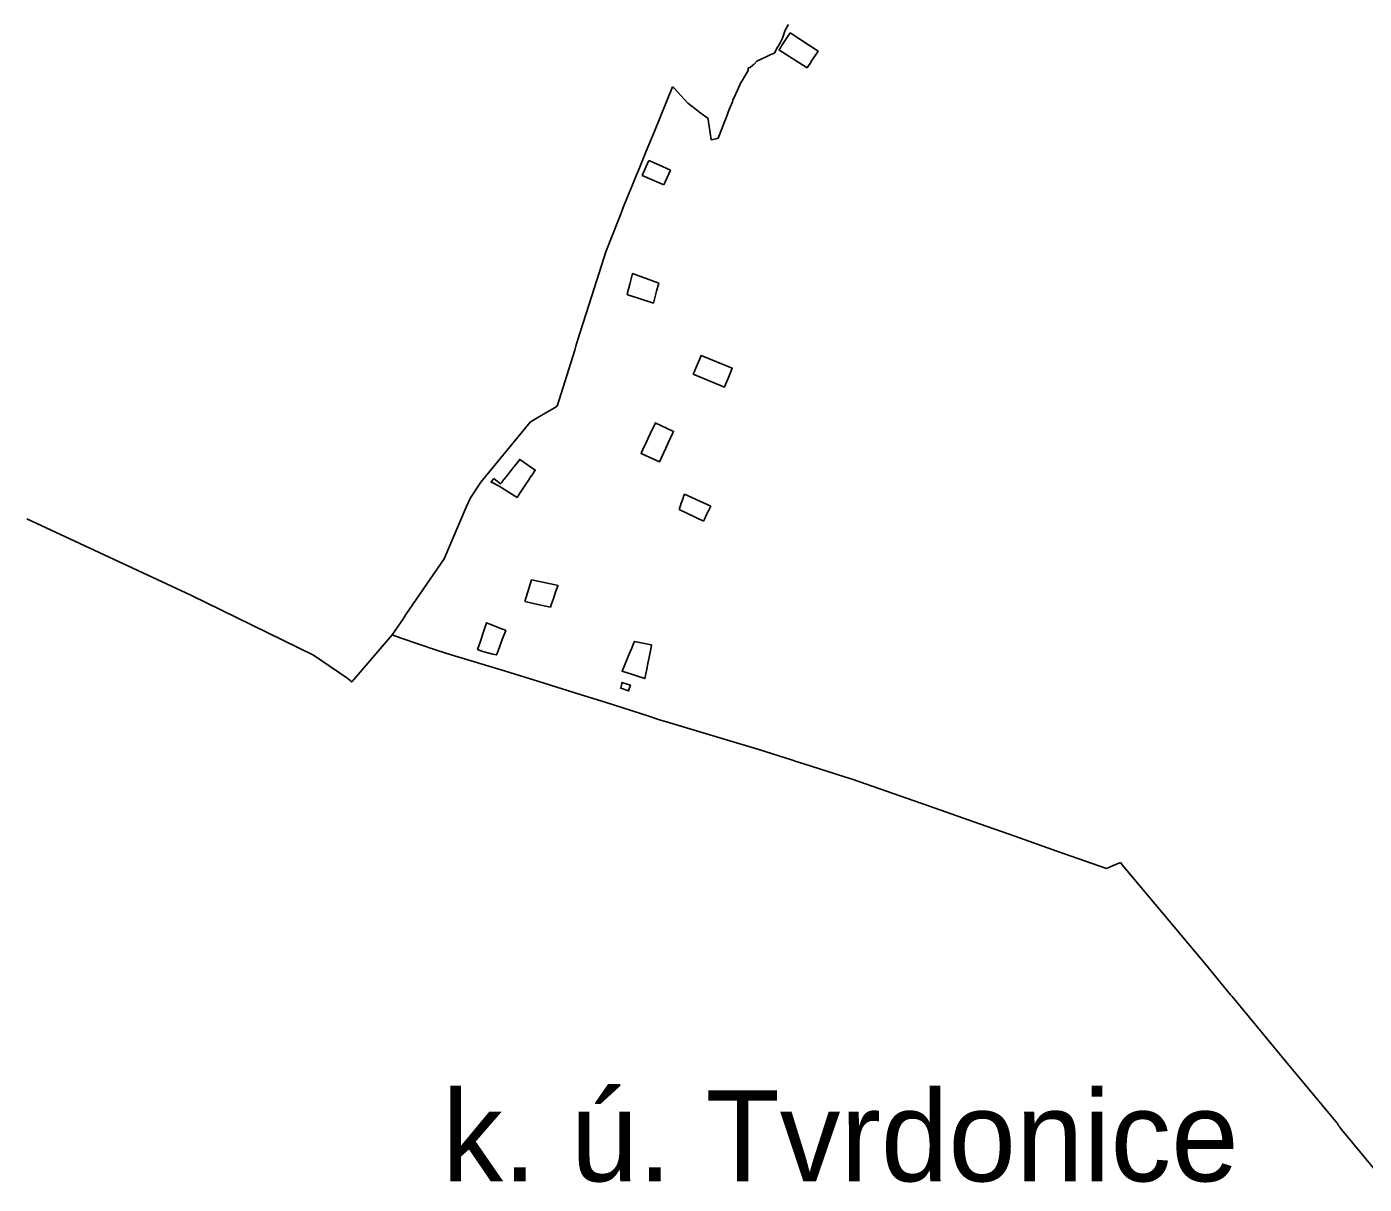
# Model space of a CAD drawing. Extents: x -576753 to -569967, y -1212971 to -1206577.
# Drawn here: x -576753 to -574765, y -1210492 to -1208771 of the extents above; entities that cross this region are included whole.
import ezdxf

# ---------------------------------------------------------------- set-up
doc = ezdxf.new("R2010")
doc.units = 0
for name, color, linetype in [('Vrstva 10', 7, 'Continuous'), ('Vrstva 13', 7, 'Continuous'), ('Vrstva 14', 7, 'Continuous'), ('Vrstva 55', 7, 'Continuous'), ('Vrstva 8', 7, 'Continuous'), ('Vrstva 9', 7, 'Continuous')]:
    doc.layers.add(name, color=color, linetype=linetype)

msp = doc.modelspace()

# ---------------------------------------------------------------- linework, layer by layer
at = {"layer": 'Vrstva 10'}
for p, q in [((-575619.3, -1208782), (-575627.2, -1208793.9)), ((-575618.3, -1208780.5), (-575619.3, -1208782)), ((-575633.8, -1208804), (-575634.9, -1208805.6)), ((-575634.9, -1208805.6), (-575593.2, -1208832.7)), ((-575630.2, -1208798.5), (-575633.8, -1208804)), ((-575627.2, -1208793.9), (-575630.2, -1208798.5)), ((-575592.4, -1208831.4), (-575588.7, -1208825.9)), ((-575588.7, -1208825.9), (-575585.9, -1208821.6)), ((-575585.9, -1208821.6), (-575577.9, -1208809.4)), ((-575593.2, -1208832.7), (-575592.4, -1208831.4)), ((-575838.3, -1208992.3), (-575828.5, -1208970.4)), ((-575828.5, -1208970.4), (-575813.6, -1208976.9)), ((-575813.6, -1208976.9), (-575796.3, -1208984.5)), ((-575796.3, -1208984.5), (-575806, -1209006.3)), ((-575823.3, -1208998.8), (-575838.3, -1208992.3)), ((-575806, -1209006.3), (-575823.3, -1208998.8)), ((-575777.3, -1209471.7), (-575776.8, -1209470)), ((-575776.8, -1209470), (-575775.7, -1209467.2)), ((-575747.3, -1209506.5), (-575783.2, -1209489.2)), ((-575741, -1209493.7), (-575743.6, -1209498.8)), ((-575739.8, -1209491.2), (-575741, -1209493.7)), ((-575737.2, -1209486), (-575739.8, -1209491.2)), ((-575736.2, -1209483.9), (-575737.2, -1209486)), ((-575848.1, -1209735.9), (-575851.1, -1209735.1)), ((-575855.8, -1209750.1), (-575857.8, -1209755.9))]:
    msp.add_line(p, q, dxfattribs=at)
for points in [[(-575577.9, -1208809.4), (-575576.8, -1208807.7), (-575618.3, -1208780.5)], [(-575816.9, -1209164.7), (-575821.6, -1209182.3), (-575859.8, -1209169.9), (-575860.4, -1209168.6), (-575859.4, -1209165), (-575856.7, -1209154), (-575852.8, -1209138.4), (-575813.7, -1209152.8), (-575816.9, -1209164.7)], [(-575755.9, -1209272.8), (-575752.8, -1209265.3), (-575751.6, -1209262.6), (-575750.6, -1209260.2), (-575704.3, -1209279.2), (-575707, -1209285.6), (-575710, -1209292.7), (-575715.8, -1209306.7), (-575716.1, -1209307.4), (-575762.3, -1209287.8), (-575761.4, -1209285.8), (-575755.9, -1209272.8)], [(-575826.4, -1209376.7), (-575819.2, -1209361.2), (-575818.9, -1209360.4), (-575791.6, -1209372.9), (-575792.5, -1209374.9), (-575799.5, -1209390.1), (-575803.2, -1209398), (-575806.5, -1209405.3), (-575812.6, -1209418.4), (-575839.8, -1209405.8), (-575836.1, -1209397.6), (-575834, -1209393.1), (-575833.4, -1209391.8), (-575829.8, -1209384.2), (-575826.4, -1209376.7)], [(-576058.8, -1209443), (-576049.1, -1209450.7), (-576047.1, -1209448.9), (-576045.7, -1209447.1), (-576038.6, -1209438), (-576033.9, -1209432.1), (-576033.5, -1209431.5), (-576028.9, -1209425.6), (-576028.3, -1209424.8), (-576023.8, -1209419.1), (-576020.3, -1209414.7), (-575997.3, -1209430.4), (-575998.4, -1209432.1), (-576002.5, -1209438.3), (-576003.1, -1209439.1), (-576006.9, -1209444.9), (-576007.9, -1209446.4), (-576011.2, -1209451.4), (-576018.3, -1209462), (-576021.1, -1209466.3), (-576021.8, -1209467.3), (-576024.2, -1209471.2), (-576051, -1209454.2), (-576063.1, -1209448.2), (-576062.3, -1209447.3), (-576058.8, -1209443)], [(-575783.2, -1209489.2), (-575781.2, -1209483.2), (-575780.1, -1209479.9)], [(-575780.1, -1209479.9), (-575778.9, -1209476.3), (-575777.3, -1209471.7)], [(-575775.7, -1209467.2), (-575775.2, -1209466.4), (-575736.2, -1209483.9)], [(-575743.6, -1209498.8), (-575744.8, -1209501.4), (-575747.3, -1209506.5)], [(-576012.7, -1209626.1), (-576002.6, -1209593.7), (-575972.3, -1209600), (-575963.4, -1209601.9), (-575964, -1209603.7), (-575966.9, -1209612.1), (-575970.2, -1209621.2), (-575973.1, -1209629.4), (-575974.7, -1209634.1), (-575993.2, -1209630.3), (-576012.7, -1209626.1)], [(-576079.3, -1209686.4), (-576073.6, -1209669.3), (-576069.6, -1209657.5), (-576045.7, -1209666.9), (-576042.6, -1209668.2), (-576041.2, -1209668.9), (-576046.2, -1209682.4), (-576052.4, -1209699.3), (-576054.6, -1209705.2), (-576060.1, -1209704.3), (-576075.3, -1209700.4), (-576082.9, -1209697.4), (-576079.3, -1209686.4)], [(-575851.1, -1209735.1), (-575868.2, -1209729.2), (-575861.3, -1209712.8), (-575861.2, -1209712.6), (-575858, -1209704.9), (-575854.3, -1209696.2), (-575850.7, -1209687.5), (-575849.8, -1209685.2), (-575827.3, -1209689.7), (-575824.2, -1209690.3), (-575824.4, -1209691), (-575826, -1209699), (-575827.8, -1209708.5), (-575829.7, -1209718), (-575831.4, -1209726.5), (-575834.1, -1209740.4), (-575848.1, -1209735.9)], [(-575857.8, -1209755.9), (-575858.8, -1209758.7), (-575870.2, -1209754.8), (-575868.6, -1209747.6), (-575868.2, -1209746.2), (-575866.8, -1209746.6), (-575855.8, -1209750), (-575855.8, -1209750.1)]]:
    msp.add_lwpolyline(points, dxfattribs=at)
at = {"layer": 'Vrstva 14'}
msp.add_lwpolyline([(-576210, -1209675.4), (-576266.2, -1209741.3), (-576269.9, -1209745.5), (-576277.2, -1209739.3), (-576327, -1209705.6), (-576509.2, -1209616.2), (-576753.1, -1209502.9)], dxfattribs=at)
at = {"layer": 'Vrstva 55'}
for p, q in [((-575845.4, -1208988.8), (-575845.5, -1208989.1)), ((-575867.6, -1209042.7), (-575867.9, -1209043.3)), ((-575867.9, -1209043.3), (-575867.7, -1209043.1))]:
    msp.add_line(p, q, dxfattribs=at)
at = {"layer": 'Vrstva 8'}
for p, q in [((-575626.2, -1208778.2), (-575629.6, -1208788.3)), ((-575625.6, -1208776.7), (-575625.9, -1208777.5)), ((-575637, -1208801.9), (-575640.4, -1208808.2)), ((-575633.8, -1208796.1), (-575637, -1208801.9)), ((-575631.2, -1208791.2), (-575633.8, -1208796.1)), ((-575629.6, -1208788.3), (-575631.2, -1208791.2)), ((-575672, -1208826.8), (-575673.2, -1208827.9)), ((-575667.6, -1208822.8), (-575672, -1208826.8)), ((-575666, -1208821.4), (-575667.6, -1208822.8)), ((-575654.1, -1208816.1), (-575666, -1208821.4)), ((-575646.9, -1208812.9), (-575654.1, -1208816.1)), ((-575641.8, -1208810.7), (-575646.9, -1208812.9)), ((-575640.4, -1208808.2), (-575641.8, -1208810.7)), ((-575680.9, -1208836.6), (-575682.2, -1208838.8)), ((-575678.5, -1208832.1), (-575680.9, -1208832.5)), ((-575680.9, -1208832.5), (-575680.9, -1208836.6)), ((-575677.7, -1208831.9), (-575678.5, -1208832.1)), ((-575674.5, -1208829), (-575677.7, -1208831.9)), ((-575673.2, -1208827.9), (-575674.5, -1208829)), ((-575793.4, -1208860.9), (-575820.7, -1208927.9)), ((-575791, -1208862.2), (-575793.4, -1208860.9)), ((-575770.4, -1208885), (-575791, -1208862.2)), ((-575693, -1208857.8), (-575698.7, -1208870.3)), ((-575692.4, -1208856.3), (-575693, -1208857.8)), ((-575689.2, -1208850.9), (-575692.4, -1208856.3)), ((-575763.8, -1208890), (-575770.4, -1208885)), ((-575699.6, -1208872.3), (-575703.4, -1208880.7)), ((-575698.7, -1208870.3), (-575699.6, -1208872.3)), ((-575762.5, -1208891.1), (-575763.8, -1208890)), ((-575755.2, -1208896.7), (-575762.5, -1208891.1)), ((-575752.4, -1208898.8), (-575755.2, -1208896.7)), ((-575740.3, -1208908), (-575752.4, -1208898.8)), ((-575739.5, -1208914), (-575740.3, -1208908)), ((-575738.7, -1208919.1), (-575739.5, -1208914)), ((-575735.9, -1208938.8), (-575738.7, -1208919.1)), ((-575820.7, -1208927.9), (-575832.2, -1208956.2)), ((-575735.8, -1208939.7), (-575735.9, -1208938.8)), ((-575733.4, -1208939.1), (-575735.8, -1208939.7)), ((-575729, -1208938), (-575733.4, -1208939.1)), ((-575725.5, -1208937.2), (-575729, -1208938)), ((-575832.2, -1208956.2), (-575845.4, -1208988.8)), ((-575892.3, -1209106.2), (-575901.6, -1209135.6)), ((-575901.6, -1209135.6), (-575933.9, -1209236.6)), ((-575933.9, -1209236.6), (-575937.1, -1209246.5)), ((-575938.6, -1209252.3), (-575964.8, -1209335.3)), ((-575937.1, -1209246.5), (-575938.6, -1209252.3)), ((-576004.9, -1209359.4), (-576078.1, -1209448.6)), ((-576078.1, -1209448.6), (-576093.6, -1209471.5)), ((-576093.6, -1209471.5), (-576100, -1209485.7)), ((-576100, -1209485.7), (-576132.7, -1209562.4)), ((-576210, -1209675.4), (-576196.8, -1209680.6)), ((-576196.8, -1209680.6), (-576144.2, -1209698.2)), ((-576144.2, -1209698.2), (-576122.1, -1209704.9)), ((-576122.1, -1209704.9), (-576041.3, -1209729.4)), ((-576041.3, -1209729.4), (-576027, -1209733.7)), ((-576027, -1209733.7), (-575983.8, -1209747.2)), ((-575983.8, -1209747.2), (-575930.3, -1209763.9)), ((-575930.3, -1209763.9), (-575893.2, -1209775.6)), ((-575893.2, -1209775.6), (-575828.2, -1209796.1)), ((-575828.2, -1209796.1), (-575812.6, -1209801.6)), ((-575812.6, -1209801.6), (-575797, -1209806.2)), ((-575797, -1209806.2), (-575772.2, -1209813.7)), ((-575772.2, -1209813.7), (-575717.9, -1209830.1)), ((-575717.9, -1209830.1), (-575664.8, -1209846.1)), ((-575664.8, -1209846.1), (-575614.9, -1209861.9)), ((-575614.9, -1209861.9), (-575609.3, -1209863.7)), ((-575609.3, -1209863.7), (-575598.1, -1209867.3)), ((-575598.1, -1209867.3), (-575540.7, -1209885.5)), ((-575540.7, -1209885.5), (-575531, -1209888.6)), ((-575531, -1209888.6), (-575525.9, -1209890.1)), ((-575525.9, -1209890.1), (-575424.3, -1209925.7)), ((-575424.3, -1209925.7), (-575419.8, -1209927.2)), ((-575419.8, -1209927.2), (-575353.5, -1209950.4)), ((-575353.5, -1209950.4), (-575345.1, -1209953.3)), ((-575345.1, -1209953.3), (-575284.2, -1209974.8)), ((-575284.2, -1209974.8), (-575221.9, -1209996.8)), ((-575221.9, -1209996.8), (-575148, -1210022.9)), ((-575148, -1210022.9), (-575138.9, -1210019)), ((-575138.9, -1210019), (-575127.2, -1210014.1)), ((-575127.2, -1210014.1), (-575124.6, -1210017.5)), ((-575124.6, -1210017.5), (-575000.9, -1210165.2)), ((-575000.9, -1210165.2), (-574963.5, -1210210.4)), ((-574963.5, -1210210.4), (-574961.2, -1210213.2)), ((-574961.2, -1210213.2), (-574874.3, -1210318.1)), ((-574874.3, -1210318.1), (-574804.5, -1210402.1)), ((-574804.5, -1210402.1), (-574802.5, -1210405.8)), ((-574802.5, -1210405.8), (-574801.3, -1210407.3)), ((-574801.3, -1210407.3), (-574798.6, -1210410.6)), ((-574798.6, -1210410.6), (-574731.2, -1210492.2))]:
    msp.add_line(p, q, dxfattribs=at)
at = {"layer": 'Vrstva 9'}
for p, q in [((-575625.9, -1208777.5), (-575626.2, -1208778.2)), ((-575620.9, -1208768.2), (-575625.6, -1208776.7)), ((-575682.2, -1208838.8), (-575689.2, -1208850.9)), ((-575704.2, -1208882.8), (-575708.8, -1208894.4)), ((-575703.4, -1208880.7), (-575704.2, -1208882.8)), ((-575708.8, -1208894.4), (-575713.5, -1208906.6)), ((-575720.9, -1208925.4), (-575723.4, -1208931.9)), ((-575715.9, -1208912.8), (-575720.9, -1208925.4)), ((-575713.5, -1208906.6), (-575715.9, -1208912.8)), ((-575723.4, -1208931.9), (-575725.5, -1208937.2)), ((-575845.5, -1208989.1), (-575852.6, -1209006.2)), ((-575860.1, -1209024.4), (-575867.6, -1209042.7)), ((-575852.6, -1209006.2), (-575860.1, -1209024.4)), ((-575867.7, -1209043.1), (-575870.7, -1209050.8)), ((-575874.7, -1209061), (-575892.3, -1209106.2)), ((-575870.7, -1209050.8), (-575874.7, -1209061)), ((-575971.3, -1209339.2), (-575979.2, -1209344)), ((-575964.8, -1209335.3), (-575971.3, -1209339.2)), ((-575994.3, -1209353), (-576004.9, -1209359.4)), ((-575987.3, -1209348.8), (-575994.3, -1209353)), ((-575979.2, -1209344), (-575987.3, -1209348.8)), ((-576132.7, -1209562.4), (-576189.5, -1209645.4)), ((-576194.2, -1209652.4), (-576201, -1209662.3)), ((-576189.5, -1209645.4), (-576194.2, -1209652.4)), ((-576206.6, -1209670.4), (-576210, -1209675.4)), ((-576201, -1209662.3), (-576206.6, -1209670.4))]:
    msp.add_line(p, q, dxfattribs=at)

# ---------------------------------------------------------------- texts
at = {"layer": 'Vrstva 13'}
msp.add_text('k. ú. Tvrdonice', height=135, dxfattribs=at).set_placement((-576135.4, -1210487.8))

doc.saveas('drawing.dxf')
